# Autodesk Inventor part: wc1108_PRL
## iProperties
Shininess: 64.0
Length Units: 11272
Angle Units: 11279
Time Units: 11290
Mass Units: 11286
Length Display Precision: 3
Angle Display Precision: 2
Compacted: True
Part Number: wc1108_PRL
Document SubType Name: Modeling
Created: 2004-08
Designer: John Blackburn
Manufacturer: Standard
Standards Organization: Custom
Material: Phenolic
Density: 0.0
Volumn: 0.0
Area: 0.0
PropertySet Name: Model Information
Control State: 0
Master: False
Checked Out: False
Author: John Blackburn
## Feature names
1. Revolution1
